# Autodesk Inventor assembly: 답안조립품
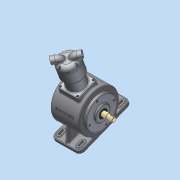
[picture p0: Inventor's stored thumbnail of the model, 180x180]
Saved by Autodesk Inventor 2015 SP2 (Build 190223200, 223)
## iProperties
Created: 2015-06
Part Number: 답안조립품
Document SubType Name: Assembly
Designer: AMC
Author: AMC
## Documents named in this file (15)
- C:\Users\AMC\Desktop\450606V1026\답안조립품.iam
- C:\Users\AMC\Desktop\450606V1026\본체.ipt
- C:\Users\AMC\Desktop\450606V1026\메인커버.ipt
- C:\Users\AMC\Desktop\450606V1026\베어링 6204.ipt
- C:\Users\AMC\Desktop\450606V1026\M4x0.7.ipt
- C:\Users\AMC\Desktop\450606V1026\메인 크랭크 축-구동부.ipt
- C:\Users\AMC\Desktop\450606V1026\크랭크 서브축.ipt
- C:\Users\AMC\Desktop\450606V1026\베어링 NA 4902.ipt
- C:\Users\AMC\Desktop\450606V1026\커넥팅 로드.ipt
- C:\Users\AMC\Desktop\450606V1026\실린더.ipt
- C:\Users\AMC\Desktop\450606V1026\실린더헤드.ipt
- C:\Users\AMC\Desktop\450606V1026\M5x0.8.ipt
- C:\Users\AMC\Desktop\450606V1026\피스톤.ipt
- C:\Users\AMC\Desktop\450606V1026\피스톤 핀.ipt
- C:\Users\AMC\Desktop\450606V1026\오일실.ipt
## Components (15 placed, 4 different names)
1. M4x0.7:1
2. M4x0.7:2
3. M4x0.7:3
4. M4x0.7:4
5. M4x0.7:5
6. M4x0.7:6
7. M4x0.7:7
8. M4x0.7:8
9. M4x0.7:9
10. M5x0.8:1
11. M5x0.8:2
12. M5x0.8:3
13. M5x0.8:4
14. 피스톤:1
15. 피스톤 핀:1
